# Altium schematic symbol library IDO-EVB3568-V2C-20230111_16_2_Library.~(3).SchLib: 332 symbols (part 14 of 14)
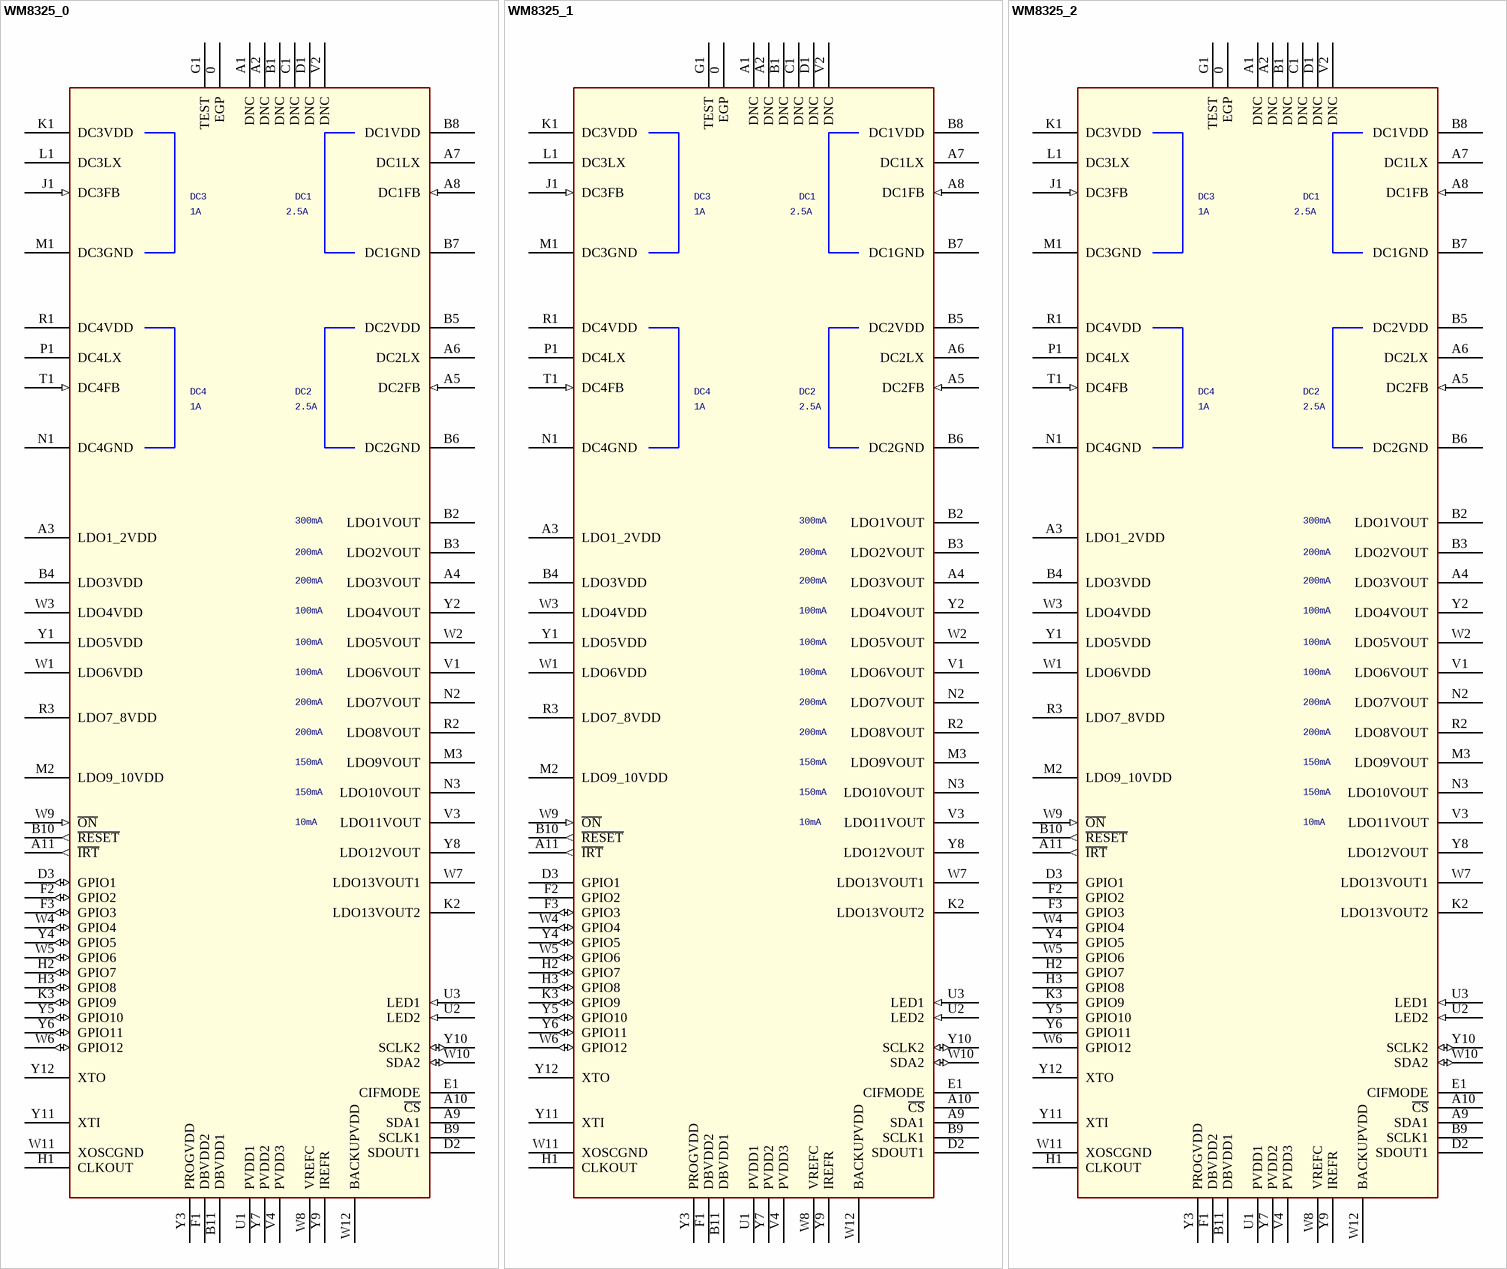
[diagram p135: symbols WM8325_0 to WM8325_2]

## WM8325_1
designator U?
Altium-Right: 240; Altium-Bottom: 740
footprint QFN81-8X8
pins: 0 EGP, A1 DNC, A2 DNC, A3 LDO1_2VDD (power), A4 LDO3VOUT (power), A5 DC2FB (in), A6 DC2LX (power), A7 DC1LX (power), A8 DC1FB (in), A9 SDA1, A10 ~{CS}, A11 ~{IRT} (out), B1 DNC, B2 LDO1VOUT (power), B3 LDO2VOUT (power), B4 LDO3VDD (power), B5 DC2VDD (power), B6 DC2GND (power), B7 DC1GND (power), B8 DC1VDD (power), B9 SCLK1, B10 ~{RESET} (out), B11 DBVDD1, C1 DNC, D1 DNC, D2 SDOUT1, D3 GPIO1, E1 CIFMODE, F1 DBVDD2, F2 GPIO2, F3 GPIO3 (io), G1 TEST, H1 CLKOUT, H2 GPIO7 (io), H3 GPIO8 (io), J1 DC3FB (in), K1 DC3VDD (power), K2 LDO13VOUT2 (power), K3 GPIO9 (io), L1 DC3LX (power), M1 DC3GND (power), M2 LDO9_10VDD (power), M3 LDO9VOUT (power), N1 DC4GND (power), N2 LDO7VOUT (power), N3 LDO10VOUT (power), P1 DC4LX (power), R1 DC4VDD (power), R2 LDO8VOUT (power), R3 LDO7_8VDD (power), T1 DC4FB (in), U1 PVDD1, U2 LED2 (in), U3 LED1 (in), V1 LDO6VOUT (power), V2 DNC, V3 LDO11VOUT (power), V4 PVDD3, W1 LDO6VDD (power), W2 LDO5VOUT (power), W3 LDO4VDD (power), W4 GPIO4 (io), W5 GPIO6 (io), W6 GPIO12 (io), W7 LDO13VOUT1 (power), W8 VREFC, W9 ~{ON} (in), W10 SDA2 (io), W11 XOSCGND, W12 BACKUPVDD, Y1 LDO5VDD (power), Y2 LDO4VOUT (power), Y3 PROGVDD, Y4 GPIO5 (io), Y5 GPIO10 (io), Y6 GPIO11 (io), Y7 PVDD2, Y8 LDO12VOUT (power), Y9 IREFR, Y10 SCLK2 (io), Y11 XTI, Y12 XTO

## WM8325_2
designator U?
Altium-Right: 240; Altium-Bottom: 740
footprint QFN81-8X8
pins: 0 EGP, A1 DNC, A2 DNC, A3 LDO1_2VDD (power), A4 LDO3VOUT (power), A5 DC2FB (in), A6 DC2LX (power), A7 DC1LX (power), A8 DC1FB (in), A9 SDA1, A10 ~{CS}, A11 ~{IRT} (out), B1 DNC, B2 LDO1VOUT (power), B3 LDO2VOUT (power), B4 LDO3VDD (power), B5 DC2VDD (power), B6 DC2GND (power), B7 DC1GND (power), B8 DC1VDD (power), B9 SCLK1, B10 ~{RESET} (out), B11 DBVDD1, C1 DNC, D1 DNC, D2 SDOUT1, D3 GPIO1, E1 CIFMODE, F1 DBVDD2, F2 GPIO2, F3 GPIO3, G1 TEST, H1 CLKOUT, H2 GPIO7, H3 GPIO8, J1 DC3FB (in), K1 DC3VDD (power), K2 LDO13VOUT2 (power), K3 GPIO9, L1 DC3LX (power), M1 DC3GND (power), M2 LDO9_10VDD (power), M3 LDO9VOUT (power), N1 DC4GND (power), N2 LDO7VOUT (power), N3 LDO10VOUT (power), P1 DC4LX (power), R1 DC4VDD (power), R2 LDO8VOUT (power), R3 LDO7_8VDD (power), T1 DC4FB (in), U1 PVDD1, U2 LED2 (in), U3 LED1 (in), V1 LDO6VOUT (power), V2 DNC, V3 LDO11VOUT (power), V4 PVDD3, W1 LDO6VDD (power), W2 LDO5VOUT (power), W3 LDO4VDD (power), W4 GPIO4, W5 GPIO6, W6 GPIO12, W7 LDO13VOUT1 (power), W8 VREFC, W9 ~{ON} (in), W10 SDA2 (io), W11 XOSCGND, W12 BACKUPVDD, Y1 LDO5VDD (power), Y2 LDO4VOUT (power), Y3 PROGVDD, Y4 GPIO5, Y5 GPIO10, Y6 GPIO11, Y7 PVDD2, Y8 LDO12VOUT (power), Y9 IREFR, Y10 SCLK2 (io), Y11 XTI, Y12 XTO

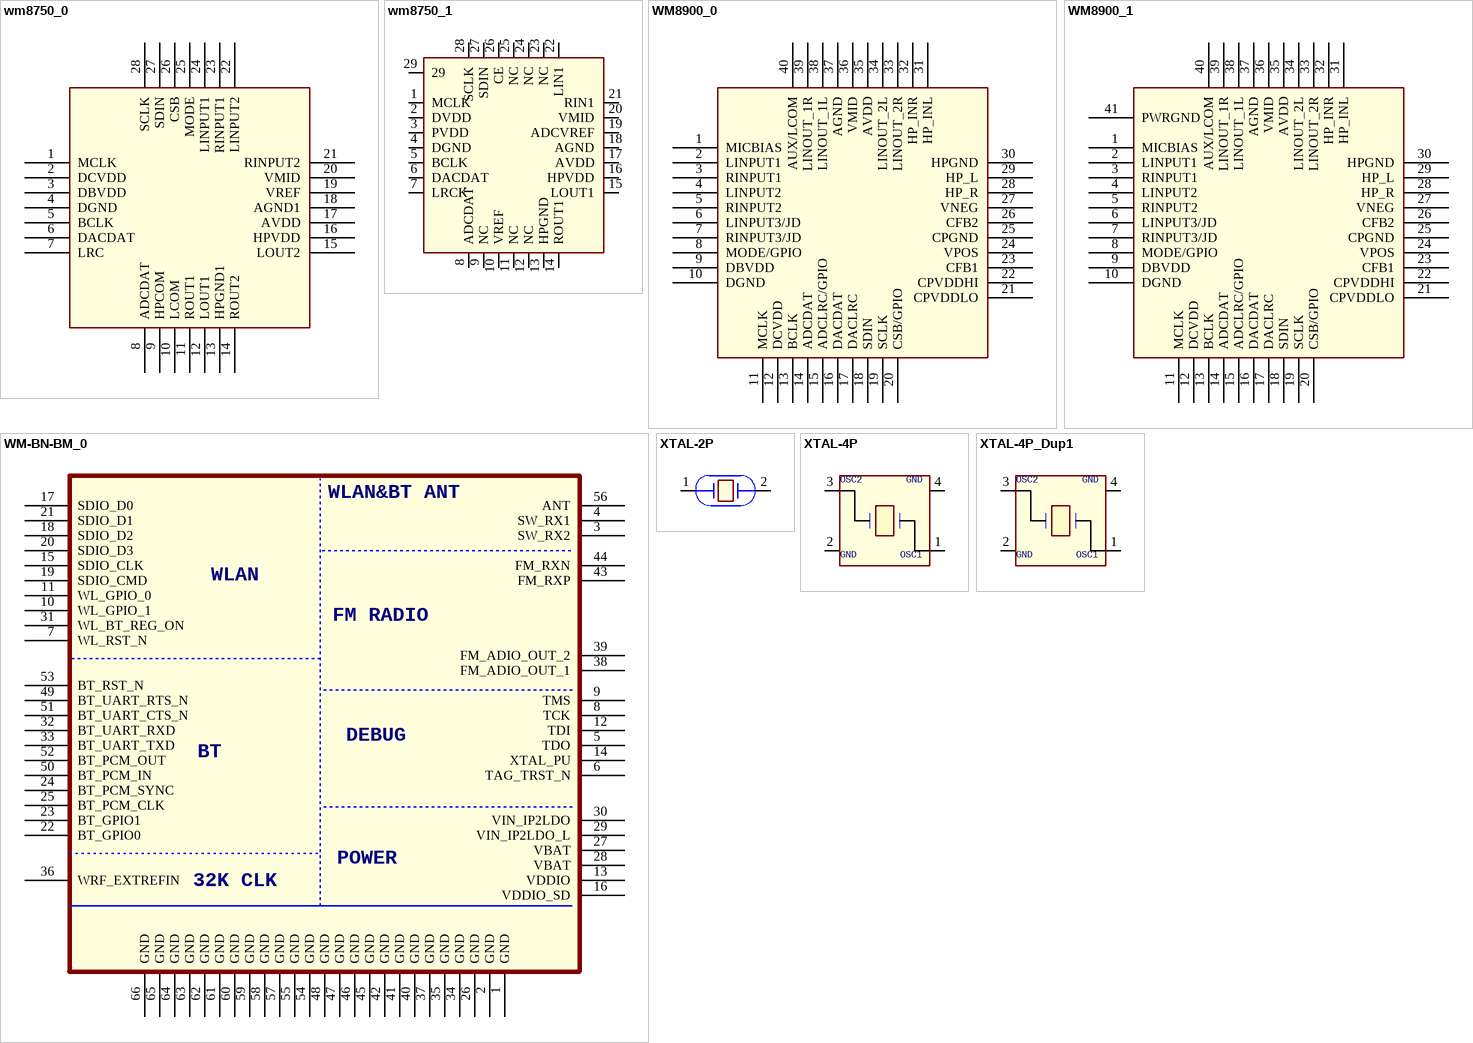
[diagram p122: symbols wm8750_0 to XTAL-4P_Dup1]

## wm8750_0
designator U?
Altium-Right: 160
pins: 1 MCLK, 2 DCVDD, 3 DBVDD, 4 DGND, 5 BCLK, 6 DACDAT, 7 LRC, 8 ADCDAT, 9 HPCOM, 10 LCOM, 11 ROUT1, 12 LOUT1, 13 HPGND1, 14 ROUT2, 15 LOUT2, 16 HPVDD, 17 AVDD, 18 AGND1, 19 VREF, 20 VMID, 21 RINPUT2, 22 LINPUT2, 23 RINPUT1, 24 LINPUT1, 25 MODE, 26 CSB, 27 SDIN, 28 SCLK

## wm8750_1
designator U?
Altium-Right: 120; Altium-Bottom: 130
pins: 1 MCLK, 2 DVDD, 3 PVDD, 4 DGND, 5 BCLK, 6 DACDAT, 7 LRCK, 8 ADCDAT, 9 NC, 10 VREF, 11 NC, 12 NC, 13 HPGND, 14 ROUT1, 15 LOUT1, 16 HPVDD, 17 AVDD, 18 AGND, 19 ADCVREF, 20 VMID, 21 RIN1, 22 LIN1, 23 NC, 24 NC, 25 NC, 26 CE, 27 SDIN, 28 SCLK, 29

## WM8900_0
designator U?
Altium-Right: 180
footprint QFN40
pins: 1 MICBIAS, 2 LINPUT1, 3 RINPUT1, 4 LINPUT2, 5 RINPUT2, 6 LINPUT3/JD, 7 RINPUT3/JD, 8 MODE/GPIO, 9 DBVDD, 10 DGND, 11 MCLK, 12 DCVDD, 13 BCLK, 14 ADCDAT, 15 ADCLRC/GPIO, 16 DACDAT, 17 DACLRC, 18 SDIN, 19 SCLK, 20 CSB/GPIO, 21 CPVDDLO, 22 CPVDDHI, 23 CFB1, 24 VPOS, 25 CPGND, 26 CFB2, 27 VNEG, 28 HP_R, 29 HP_L, 30 HPGND, 31 HP_INL, 32 HP_INR, 33 LINOUT_2R, 34 LINOUT_2L, 35 AVDD, 36 VMID, 37 AGND, 38 LINOUT_1L, 39 LINOUT_1R, 40 AUX/LCOM

## WM8900_1
designator U?
Altium-Right: 180
footprint QFN40
pins: 1 MICBIAS, 2 LINPUT1, 3 RINPUT1, 4 LINPUT2, 5 RINPUT2, 6 LINPUT3/JD, 7 RINPUT3/JD, 8 MODE/GPIO, 9 DBVDD, 10 DGND, 11 MCLK, 12 DCVDD, 13 BCLK, 14 ADCDAT, 15 ADCLRC/GPIO, 16 DACDAT, 17 DACLRC, 18 SDIN, 19 SCLK, 20 CSB/GPIO, 21 CPVDDLO, 22 CPVDDHI, 23 CFB1, 24 VPOS, 25 CPGND, 26 CFB2, 27 VNEG, 28 HP_R, 29 HP_L, 30 HPGND, 31 HP_INL, 32 HP_INR, 33 LINOUT_2R, 34 LINOUT_2L, 35 AVDD, 36 VMID, 37 AGND, 38 LINOUT_1L, 39 LINOUT_1R, 40 AUX/LCOM, 41 PWRGND

## WM-BN-BM_0
designator U?
Altium-Right: 340; Altium-Bottom: 331
footprint LGA66
pins: 1 GND, 2 GND, 3 SW_RX2, 4 SW_RX1, 5 TDO, 6 TAG_TRST_N, 7 WL_RST_N, 8 TCK, 9 TMS, 10 WL_GPIO_1, 11 WL_GPIO_0, 12 TDI, 13 VDDIO, 14 XTAL_PU, 15 SDIO_CLK, 16 VDDIO_SD, 17 SDIO_D0, 18 SDIO_D2, 19 SDIO_CMD, 20 SDIO_D3, 21 SDIO_D1, 22 BT_GPIO0, 23 BT_GPIO1, 24 BT_PCM_SYNC, 25 BT_PCM_CLK, 26 GND, 27 VBAT, 28 VBAT, 29 VIN_IP2LDO_L, 30 VIN_IP2LDO, 31 WL_BT_REG_ON, 32 BT_UART_RXD, 33 BT_UART_TXD, 34 GND, 35 GND, 36 WRF_EXTREFIN, 37 GND, 38 FM_ADIO_OUT_1, 39 FM_ADIO_OUT_2, 40 GND, 41 GND, 42 GND, 43 FM_RXP, 44 FM_RXN, 45 GND, 46 GND, 47 GND, 48 GND, 49 BT_UART_RTS_N, 50 BT_PCM_IN, 51 BT_UART_CTS_N, 52 BT_PCM_OUT, 53 BT_RST_N, 54 GND, 55 GND, 56 ANT, 57 GND, 58 GND, 59 GND, 60 GND, 61 GND, 62 GND, 63 GND, 64 GND, 65 GND, 66 GND

## XTAL-2P
designator XT?
CLASS: IC; Altium-Right: 40; Altium-Bottom: 20
pins: 1, 2

## XTAL-4P
designator XT?
CLASS: IC; Altium-Right: 60
pins: 1, 2, 3, 4

## XTAL-4P_Dup1
designator XT?
CLASS: IC; Altium-Right: 60
pins: 1, 2, 3, 4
